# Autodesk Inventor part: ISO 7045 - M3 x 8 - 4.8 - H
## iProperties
Comments: To add or edit properties for Autodesk Inventor files, use iProperties.
Created: 2004-08
Part Number: ISO 7045 - M3 x 8 - 4.8 - H
Vendor: Autodesk Inc.
Document SubType Name: Modeling
Designer: John Blackburn
Material: Default
Description: Recessed Pan Head Screw
Standard: ISO 7045
Size Designation: M3 x 8 - 4.8 - H
Alert: To add or edit properties for Autodesk Inventor files, use iProperties.
Control State: 0
Master: False
Checked Out: False
Shininess: 64.0
Length Units: 11269
Angle Units: 11279
Time Units: 11290
Mass Units: 11283
Length Display Precision: 3
Angle Display Precision: 2
Compacted: True
EGR: 1
Density: 0.0
Volumn: 0.0
Area: 0.0
PropertySet Name: Model Information
Author: John Blackburn
Revision Number: 8
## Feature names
1. Body [Revolution]
2. Slot [Extrusion]
3. Cut [Revolution]
4. Fillet1
5. Fillet2
6. Chamfer1
